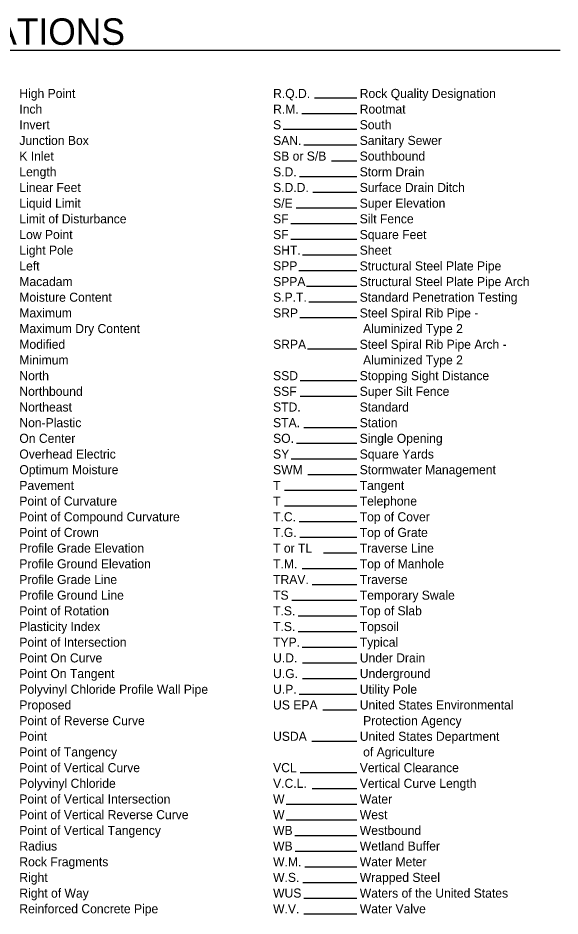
# Model space of a CAD drawing. Extents: x 1.3 to 42.5, y -2.5 to 22.6.
# Drawn here: x 9.32 to 16.49, y 9.27 to 21.15 of the extents above; entities that cross this region are included whole.
import ezdxf

# ---------------------------------------------------------------- set-up
doc = ezdxf.new("R2010")
doc.units = 0
doc.layers.add('G-ANNO-NOTE', color=7, linetype='Continuous')

msp = doc.modelspace()

# ---------------------------------------------------------------- linework, layer by layer
at = {"layer": 'G-ANNO-NOTE'}
for p, q in [((2.497, 20.725), (16.488, 20.725)), ((13.24, 20.092), (13.799, 20.092)), ((13.073, 19.885), (13.799, 19.885)), ((12.824, 19.677), (13.799, 19.677)), ((13.098, 19.47), (13.799, 19.47)), ((13.465, 19.262), (13.799, 19.262)), ((13.043, 19.055), (13.799, 19.055)), ((13.22, 18.847), (13.799, 18.847)), ((12.997, 18.64), (13.799, 18.64)), ((12.928, 18.432), (13.799, 18.432)), ((12.928, 18.224), (13.799, 18.224)), ((13.082, 18.017), (13.799, 18.017)), ((13.032, 17.809), (13.799, 17.809)), ((13.134, 17.602), (13.799, 17.602)), ((13.166, 17.394), (13.799, 17.394)), ((13.045, 17.186), (13.799, 17.186)), ((13.147, 16.771), (13.799, 16.771)), ((13.051, 16.356), (13.799, 16.356)), ((13.051, 16.148), (13.799, 16.148)), ((13.098, 15.733), (13.799, 15.733)), ((13.003, 15.526), (13.799, 15.526)), ((12.932, 15.318), (13.799, 15.318)), ((13.15, 15.11), (13.799, 15.11)), ((12.843, 14.903), (13.799, 14.903)), ((12.843, 14.695), (13.799, 14.695)), ((13.035, 14.487), (13.799, 14.487)), ((13.046, 14.28), (13.799, 14.28)), ((13.359, 14.072), (13.799, 14.072)), ((13.077, 13.865), (13.799, 13.865)), ((13.211, 13.657), (13.799, 13.657)), ((12.939, 13.449), (13.799, 13.449)), ((13.023, 13.242), (13.799, 13.242)), ((13.023, 13.034), (13.799, 13.034)), ((13.076, 12.827), (13.799, 12.827)), ((13.083, 12.619), (13.799, 12.619)), ((13.083, 12.411), (13.799, 12.411)), ((13.037, 12.204), (13.799, 12.204)), ((13.348, 11.996), (13.799, 11.996)), ((13.203, 11.581), (13.799, 11.581)), ((13.051, 11.166), (13.799, 11.166)), ((13.21, 10.958), (13.799, 10.958)), ((12.866, 10.751), (13.799, 10.751)), ((12.866, 10.543), (13.799, 10.543)), ((12.98, 10.335), (13.799, 10.335)), ((12.984, 10.128), (13.799, 10.128)), ((13.112, 9.92), (13.799, 9.92)), ((13.085, 9.713), (13.799, 9.713)), ((13.099, 9.505), (13.799, 9.505)), ((13.097, 9.297), (13.799, 9.297))]:
    msp.add_line(p, q, dxfattribs=at)

# ---------------------------------------------------------------- texts
for s, height, p in [('ABBREVIATIONS', 0.35, (6.961, 20.795)), ('High Point', 0.12, (9.335, 20.092)), ('R.Q.D.', 0.12, (12.692, 20.092)), ('Rock Quality Designation', 0.12, (13.838, 20.092)), ('Inch', 0.12, (9.335, 19.885)), ('R.M.', 0.12, (12.692, 19.885)), ('Rootmat', 0.12, (13.838, 19.885)), ('Invert', 0.12, (9.335, 19.678)), ('S', 0.12, (12.692, 19.678)), ('South', 0.12, (13.838, 19.678)), ('Junction Box', 0.12, (9.335, 19.47)), ('SAN.', 0.12, (12.692, 19.47)), ('Sanitary Sewer', 0.12, (13.838, 19.47)), ('K Inlet', 0.12, (9.335, 19.263)), ('SB or S/B', 0.12, (12.692, 19.263)), ('Southbound', 0.12, (13.838, 19.263)), ('Length', 0.12, (9.335, 19.055)), ('S.D.', 0.12, (12.692, 19.055)), ('Storm Drain', 0.12, (13.838, 19.055)), ('Linear Feet', 0.12, (9.335, 18.848)), ('S.D.D.', 0.12, (12.692, 18.848)), ('Surface Drain Ditch', 0.12, (13.838, 18.848)), ('Liquid Limit', 0.12, (9.335, 18.64)), ('S/E', 0.12, (12.692, 18.64)), ('Super Elevation', 0.12, (13.838, 18.64)), ('Limit of Disturbance', 0.12, (9.335, 18.433)), ('SF', 0.12, (12.692, 18.433)), ('Silt Fence', 0.12, (13.838, 18.433)), ('Low Point', 0.12, (9.335, 18.225)), ('SF', 0.12, (12.692, 18.225)), ('Square Feet', 0.12, (13.838, 18.225)), ('Light Pole', 0.12, (9.335, 18.018)), ('SHT.', 0.12, (12.692, 18.018)), ('Sheet', 0.12, (13.838, 18.018)), ('Left', 0.12, (9.335, 17.81)), ('SPP', 0.12, (12.692, 17.811)), ('Structural Steel Plate Pipe', 0.12, (13.838, 17.81)), ('Macadam', 0.12, (9.335, 17.603)), ('SPPA', 0.12, (12.692, 17.603)), ('Structural Steel Plate Pipe Arch', 0.12, (13.838, 17.603)), ('Moisture Content', 0.12, (9.335, 17.396)), ('S.P.T.', 0.12, (12.692, 17.396)), ('Standard Penetration Testing', 0.12, (13.838, 17.396)), ('Maximum', 0.12, (9.335, 17.188)), ('SRP', 0.12, (12.692, 17.188)), ('Steel Spiral Rib Pipe - ', 0.12, (13.838, 17.188)), ('Maximum Dry Content', 0.12, (9.335, 16.981)), (' Aluminized Type 2', 0.12, (13.838, 16.981)), ('Modified', 0.12, (9.335, 16.773)), ('SRPA', 0.12, (12.692, 16.773)), ('Steel Spiral Rib Pipe Arch - ', 0.12, (13.838, 16.773)), ('Minimum', 0.12, (9.335, 16.566)), (' Aluminized Type 2', 0.12, (13.838, 16.566)), ('North', 0.12, (9.335, 16.358)), ('SSD', 0.12, (12.692, 16.358)), ('Stopping Sight Distance', 0.12, (13.838, 16.358)), ('Northbound', 0.12, (9.335, 16.151)), ('SSF', 0.12, (12.692, 16.151)), ('Super Silt Fence', 0.12, (13.838, 16.151)), ('Northeast', 0.12, (9.335, 15.943)), ('STD.', 0.12, (12.692, 15.943)), ('Standard', 0.12, (13.838, 15.943)), ('Non-Plastic', 0.12, (9.335, 15.736)), ('STA.', 0.12, (12.692, 15.736)), ('Station', 0.12, (13.838, 15.736)), ('On Center', 0.12, (9.335, 15.529)), ('SO.', 0.12, (12.692, 15.529)), ('Single Opening', 0.12, (13.838, 15.529)), ('Overhead Electric', 0.12, (9.335, 15.321)), ('Square Yards', 0.12, (13.838, 15.321)), ('SY', 0.12, (12.692, 15.321)), ('Optimum Moisture', 0.12, (9.335, 15.114)), ('SWM', 0.12, (12.692, 15.114)), ('Stormwater Management', 0.12, (13.838, 15.114)), ('Pavement', 0.12, (9.335, 14.906)), ('T', 0.12, (12.692, 14.906)), ('Tangent', 0.12, (13.838, 14.906)), ('Point of Curvature', 0.12, (9.335, 14.699)), ('T', 0.12, (12.692, 14.699)), ('Telephone', 0.12, (13.838, 14.699)), ('Point of Compound Curvature', 0.12, (9.335, 14.491)), ('Top of Cover', 0.12, (13.838, 14.491)), ('T.C.', 0.12, (12.692, 14.491)), ('Point of Crown', 0.12, (9.335, 14.284)), ('T.G.', 0.12, (12.692, 14.284)), ('Top of Grate', 0.12, (13.838, 14.284)), ('Profile Grade Elevation', 0.12, (9.335, 14.076)), ('T or TL', 0.12, (12.692, 14.076)), ('Traverse Line', 0.12, (13.838, 14.076)), ('Profile Ground Elevation', 0.12, (9.335, 13.869)), ('T.M.', 0.12, (12.692, 13.869)), ('Top of Manhole', 0.12, (13.839, 13.869)), ('Profile Grade Line', 0.12, (9.335, 13.661)), ('TRAV.', 0.12, (12.692, 13.662)), ('Traverse', 0.12, (13.839, 13.661)), ('Profile Ground Line', 0.12, (9.335, 13.454)), ('TS', 0.12, (12.692, 13.454)), ('Temporary Swale', 0.12, (13.839, 13.454)), ('Point of Rotation', 0.12, (9.335, 13.247)), ('T.S.', 0.12, (12.692, 13.247)), ('Top of Slab', 0.12, (13.839, 13.247)), ('Plasticity Index', 0.12, (9.335, 13.039)), ('T.S.', 0.12, (12.692, 13.039)), ('Topsoil', 0.12, (13.839, 13.039)), ('Point of Intersection', 0.12, (9.335, 12.832)), ('TYP.', 0.12, (12.692, 12.832)), ('Typical', 0.12, (13.839, 12.832)), ('Point On Curve', 0.12, (9.335, 12.624)), ('U.D.', 0.12, (12.692, 12.624)), ('Under Drain', 0.12, (13.839, 12.624)), ('Point On Tangent', 0.12, (9.335, 12.417)), ('U.G.', 0.12, (12.692, 12.417)), ('Underground', 0.12, (13.839, 12.417)), ('Polyvinyl Chloride Profile Wall Pipe', 0.12, (9.335, 12.209)), ('U.P.', 0.12, (12.692, 12.209)), ('Utility Pole', 0.12, (13.839, 12.209)), ('Proposed', 0.12, (9.335, 12.002)), ('US EPA', 0.12, (12.692, 12.002)), ('United States Environmental', 0.12, (13.839, 12.002)), ('Point of Reverse Curve', 0.12, (9.335, 11.794)), (' Protection Agency', 0.12, (13.839, 11.794)), ('Point', 0.12, (9.335, 11.587)), ('USDA', 0.12, (12.692, 11.587)), ('United States Department', 0.12, (13.839, 11.587)), ('Point of Tangency', 0.12, (9.335, 11.38)), (' of Agriculture', 0.12, (13.839, 11.38)), ('Point of Vertical Curve', 0.12, (9.335, 11.172)), ('VCL', 0.12, (12.692, 11.172)), ('Vertical Clearance', 0.12, (13.839, 11.172)), ('Polyvinyl Chloride', 0.12, (9.335, 10.965)), ('V.C.L.', 0.12, (12.692, 10.965)), ('Vertical Curve Length', 0.12, (13.839, 10.965)), ('Point of Vertical Intersection', 0.12, (9.335, 10.757)), ('W', 0.12, (12.692, 10.757)), ('Water', 0.12, (13.839, 10.757)), ('Point of Vertical Reverse Curve', 0.12, (9.335, 10.55)), ('W', 0.12, (12.692, 10.55)), ('West', 0.12, (13.839, 10.55)), ('Point of Vertical Tangency', 0.12, (9.335, 10.342)), ('WB', 0.12, (12.692, 10.342)), ('Westbound', 0.12, (13.839, 10.342)), ('Radius', 0.12, (9.335, 10.135)), ('WB', 0.12, (12.692, 10.135)), ('Wetland Buffer', 0.12, (13.839, 10.135)), ('Rock Fragments', 0.12, (9.335, 9.927)), ('W.M.', 0.12, (12.692, 9.927)), ('Water Meter', 0.12, (13.839, 9.927)), ('Right', 0.12, (9.335, 9.72)), ('W.S.', 0.12, (12.692, 9.72)), ('Wrapped Steel', 0.12, (13.839, 9.72)), ('Right of Way', 0.12, (9.335, 9.512)), ('WUS', 0.12, (12.692, 9.513)), ('Waters of the United States', 0.12, (13.839, 9.512)), ('Reinforced Concrete Pipe ', 0.12, (9.335, 9.305)), ('W.V.', 0.12, (12.692, 9.305)), ('Water Valve', 0.12, (13.839, 9.305))]:
    msp.add_text(s, height=height, rotation=0.0015, dxfattribs=at).set_placement(p)

doc.saveas('drawing.dxf')
